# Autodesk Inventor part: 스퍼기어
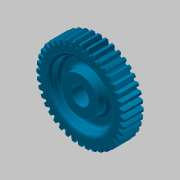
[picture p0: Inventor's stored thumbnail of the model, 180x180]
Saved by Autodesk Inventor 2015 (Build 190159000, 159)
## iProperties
Created: 2018-11
Part Number: 스퍼기어
Material: 알루미늄 6061
Document SubType Name: Modeling
Designer: mduedu
Categories: <?xml version="1.0" encoding="UTF-16"?> <MemberInstance><Categories><FamilyTemplate><FamilyTemplateParameter ValueType="xs:double" Id="1" ObjectReferenceKey="da
Density: 1 g/cm^3
Appearance: 하늘색 중간
CustomPartVersion: 1
Author: mduedu
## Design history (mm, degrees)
sketch "Sketch1"
  geometry: C1 r 42 at (0, 0)
  constraints: 1 centre point
  dimensions: "d0" = 83.99905 diameter of C1 (= da_da)
extrude "Extrusion1" new body sketch "Sketch1" distance "d1" = 19 (= da_b); taper "d2" = 0 deg
workplane "Work Plane2"
sketch "Sketch2"
  geometry: C1 r 42 at (0, 0) reference; C2 r 40.05 at (0, 0)
  constraints: 1 centre point, 1 coincident
  dimensions: "d3" = 80.10038 diameter of C2 (= da_dw)
feature "피치 지름" sketch "Sketch2" dims "d4" = 10, "d5" = 0
workplane "Work Plane8"
workplane "Work Plane9"
feature "스퍼 기어" dims "da_b" = 19, "da_d" = 80, "da_aw" = 80.10038, "da_da" = 83.99905, "da_df" = 75, "da_dw" = 80.10038, angle "da_beta" = 0 deg, "da_lefttooth" = 0, "da_righttooth" = 0
sketch "스케치3"
  geometry: L1 (-42, 19)-(42, 19) reference; L2 (42, 19)-(42, 0) reference; L3 (42, 0)-(-42, 0) reference; L4 (-42, 0)-(-42, 19) reference; L5 (0, 0)-(0, 19); L6 (42, 0)-(41, 0); L7 (42, 1)-(42, 0); L8 (42, 19)-(41, 19); L9 (42, 18)-(42, 19); L10 (41, 19)-(42, 18); L11 (41, 0)-(42, 1)
  constraints: 14 end point, 2 horizontal, 2 vertical, 1 midpoint
  dimensions: "d49" = 1 distance from line of L8.end L2; "d50" = 1 horizontal distance of L8.end L9.start; "d51" = 1 horizontal distance of L6.end L7.start; "d52" = 1 horizontal distance of L6.end L7.start
revolve "회전1" sketch "스케치3" stored, may be unused: angle "d53" = 90 deg
sketch "스케치4"
  geometry: L1 (-2.5, 8.124)-(2.5, 8.124); L2 (2.5, 8.124)-(2.5, 10.8); L3 (2.5, 10.8)-(-2.5, 10.8); L4 (-2.5, 10.8)-(-2.5, 8.124); A1 r 8.5 centre (0, 0) between (-2.5, 8.124) and (2.5, 8.124); 1 further point
  constraints: 8 end point, 2 parallel, 2 point on circle, 1 centre point, 1 coincident, 1 horizontal, 1 perpendicular
  dimensions: "d54" = 17 diameter of A1; "d56" = 19.3 dimension on A1 L3; "d57" = 5 distance of L2.end L3.end
extrude "돌출2" cut sketch "스케치4" stored distance "d58" = 10; taper "d59" = 0 deg
chamfer "모따기1" distance "d60" = 1; stored, may be unused: second distance "d61" = 2, angle "d62" = 45 deg
sketch "스케치5"
  geometry: C1 r 17.5 at (0, 0); C2 r 28.5 at (0, 0); 1 further point
  constraints: 2 centre point, 2 coincident
  dimensions: "d63" = 35 diameter of C1; "d64" = 57 diameter of C2
extrude "돌출3" cut sketch "스케치5" distance "d65" = 9.5; taper "d66" = 0 deg
fillet "모깎기1" dims "d67" = 3
body "Solid1"
body "Srf1"
node "절단 모서리 투영1"
other parameters: "d16" = 80.10038 (= da_aw), "d17" = 0, "d34" = 4.5 deg (computed from da_z), "d39" = 0, "d41" = 0, "d43" = 80.10038 (= da_aw), "d46" = 80.10038 (= da_aw), "d47" = 0, "d48" = 0
